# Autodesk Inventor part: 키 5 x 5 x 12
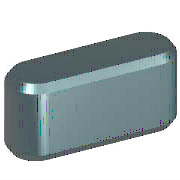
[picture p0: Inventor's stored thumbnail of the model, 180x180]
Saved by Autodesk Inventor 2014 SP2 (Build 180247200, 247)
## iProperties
Created: 2012-02
Part Number: 키 5 x 5 x 12
Material: 강철, 연강
Description: 키 및 해당 키홈
Document SubType Name: Modeling
Standard: KS B 1311
Designer: mduedu
Standards Organization: KS
Language: ko-KR
Size Designation: 5 x 5 x 12
Categories: <MemberInstance><Categories><Category DisplayName="샤프트 부품" InternalName="7f7aeb1f-a693-4053-b835-cee3144e0d98" Mnemonic="SHFT"><Category DisplayName="키" Interna
Density: 1 g/cm^3
Appearance: 노란색
IsCustomPart: 1
Author: mduedu
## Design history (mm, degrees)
workplane "Work Plane1"
workplane "Work Plane2"
sketch "스케치1"
  geometry: L1 (2.5, 2.5)-(9.5, 2.5); L2 (9.5, -2.5)-(2.5, -2.5); L3 (0, 9.4)-(0, -7.4) reference; L4 (-5, 0)-(30, 0) reference; L5 (12, 0)-(12, 7); A1 r 2.5 centre (2.5, 0) between (2.5, 2.5) and (2.5, -2.5); A2 r 2.5 centre (9.5, 0) between (9.5, -2.5) and (9.5, 2.5)
  constraints: 6 end point, 5 point on circle, 4 tangent, 3 point on line, 2 centre point, 1 horizontal, 1 parallel, 1 perpendicular
  dimensions: "d0" = 2.5 radius of A1 (= 0.5 x PB); "d13" = 2.5 radius of A2 (= 0.5 x PB); "d14" = 12 distance between parallel lines of L5 L3 (= NLG)
extrude "본체1" new body sketch "스케치1" taper "d3" = 0 deg; stored distance "d4" = 10
workplane "Work Plane3"
body "Solid1"
chamfer "모따기1" distance "d8" = 0.4 (= PHH); stored, may be unused: second distance "d9" = 0.4 (= PHH), angle "d15" = 45 deg
other parameters: "d1" = -3 (= -PNT), "d2" = 2 (= PH - PNT), "NLG" = 12 [user parameter; used in 3 equation terms], "PB" = 5 [user parameter; used in 2 equation terms], "PNT" = 3 [user parameter; used in 2 equation terms], "PH" = 5 [user parameter; used in 1 equation term], "PHH" = 0.4 [user parameter; used in 2 equation terms], "d10" = 0, "d16" = 0, "d17" = 0, "d18" = 0, "WDMIN" = 12 [user parameter], "PLB2" = 12 (= NLG) [user parameter], "WDMAX" = 17 [user parameter], "PLB1" = 12 (= NLG) [user parameter], "RR" = 0.16 [user parameter], "PUEB" = 2.3 [user parameter]
